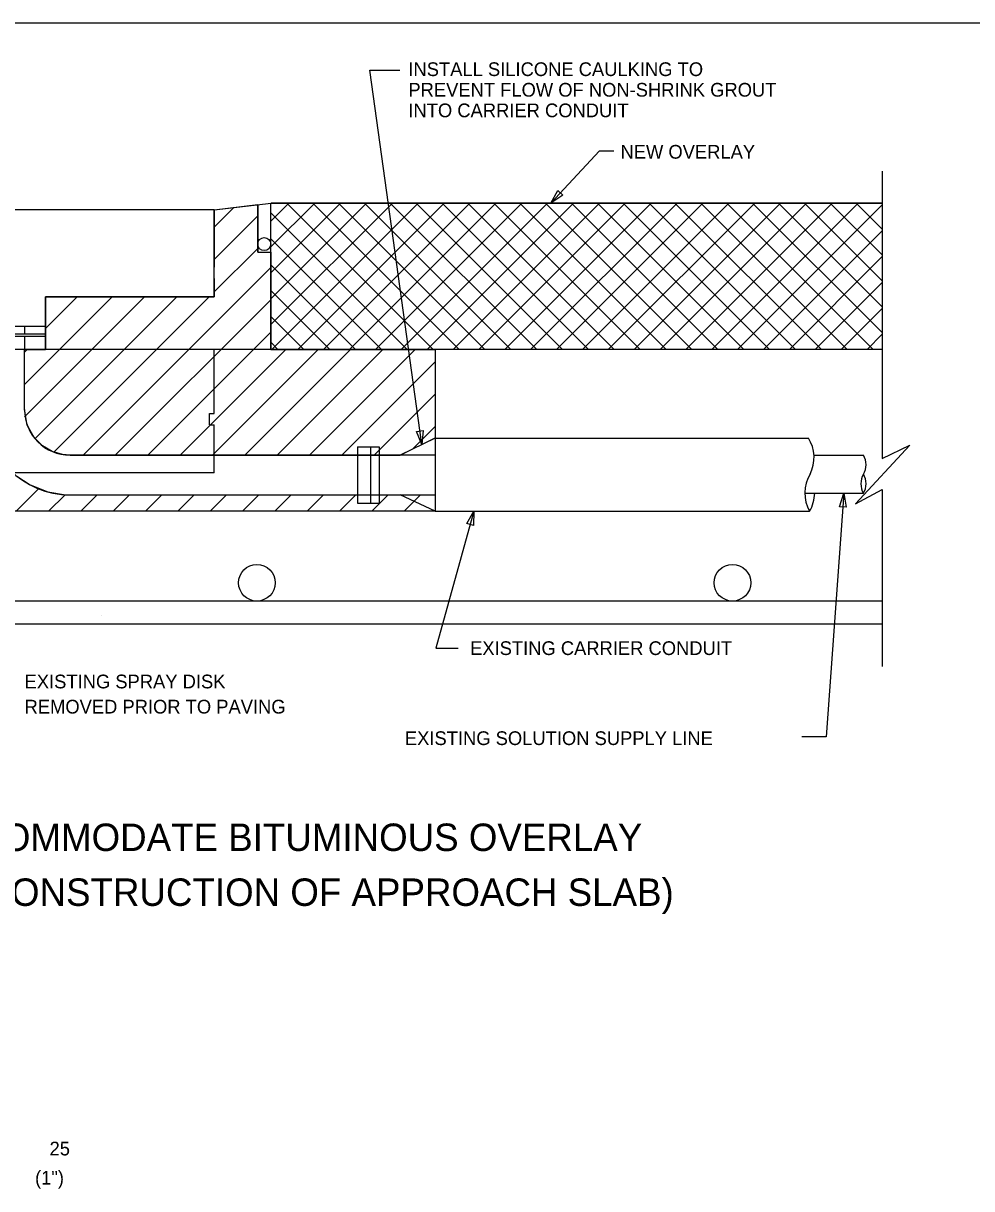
# Model space of a CAD drawing. Extents: x 3239 to 4230, y -4276 to -2494.
# Drawn here: x 3464.4 to 3671.7, y -3952 to -3697.3 of the extents above; entities that cross this region are included whole.
import ezdxf

# ---------------------------------------------------------------- set-up
doc = ezdxf.new("R2010")
doc.units = 0
for name, color, linetype in [('1', 7, 'Continuous'), ('2', 7, 'Continuous'), ('3', 7, 'Continuous')]:
    doc.layers.add(name, color=color, linetype=linetype)

msp = doc.modelspace()

# ---------------------------------------------------------------- linework, layer by layer
at = {"layer": '2'}
for p, q in [((4065.03, -3697.29), (3279.03, -3697.29)), ((3652.12, -3729.58), (3652.12, -3792.42)), ((3506.07, -3738.07), (3518.57, -3736.57)), ((3515.6, -3747.29), (3515.6, -3736.93)), ((3518.47, -3768.57), (3518.47, -3736.57)), ((3518.47, -3740.52), (3522.41, -3736.57)), ((3518.47, -3746.17), (3528.07, -3736.57)), ((3518.47, -3751.83), (3533.73, -3736.57)), ((3518.47, -3757.49), (3539.38, -3736.57)), ((3518.47, -3763.14), (3545.04, -3736.57)), ((3652.12, -3736.57), (3518.57, -3736.57)), ((3518.7, -3768.57), (3550.7, -3736.57)), ((3521.96, -3736.57), (3553.96, -3768.57)), ((3524.35, -3768.57), (3556.35, -3736.57)), ((3527.62, -3736.57), (3559.62, -3768.57)), ((3530.01, -3768.57), (3562.01, -3736.57)), ((3533.28, -3736.57), (3565.28, -3768.57)), ((3535.67, -3768.57), (3567.67, -3736.57)), ((3538.93, -3736.57), (3570.93, -3768.57)), ((3541.33, -3768.57), (3573.33, -3736.57)), ((3544.59, -3736.57), (3576.59, -3768.57)), ((3546.98, -3768.57), (3578.98, -3736.57)), ((3550.25, -3736.57), (3582.25, -3768.57)), ((3552.64, -3768.57), (3584.64, -3736.57)), ((3555.9, -3736.57), (3587.9, -3768.57)), ((3558.3, -3768.57), (3590.3, -3736.57)), ((3561.56, -3736.57), (3593.56, -3768.57)), ((3563.95, -3768.57), (3595.95, -3736.57)), ((3567.22, -3736.57), (3599.22, -3768.57)), ((3569.61, -3768.57), (3601.61, -3736.57)), ((3572.88, -3736.57), (3604.88, -3768.57)), ((3575.27, -3768.57), (3607.27, -3736.57)), ((3578.53, -3736.57), (3610.53, -3768.57)), ((3580.92, -3768.57), (3612.92, -3736.57)), ((3584.19, -3736.57), (3616.19, -3768.57)), ((3586.58, -3768.57), (3618.58, -3736.57)), ((3589.85, -3736.57), (3621.85, -3768.57)), ((3592.24, -3768.57), (3624.24, -3736.57)), ((3595.5, -3736.57), (3627.5, -3768.57)), ((3597.89, -3768.57), (3629.89, -3736.57)), ((3601.16, -3736.57), (3633.16, -3768.57)), ((3603.55, -3768.57), (3635.55, -3736.57)), ((3606.82, -3736.57), (3638.82, -3768.57)), ((3609.21, -3768.57), (3641.21, -3736.57)), ((3612.47, -3736.57), (3644.47, -3768.57)), ((3614.86, -3768.57), (3646.86, -3736.57)), ((3618.13, -3736.57), (3650.13, -3768.57)), ((3620.52, -3768.57), (3652.12, -3736.98)), ((3623.79, -3736.57), (3652.12, -3764.9)), ((3629.44, -3736.57), (3652.12, -3759.24)), ((3635.1, -3736.57), (3652.12, -3753.59)), ((3640.76, -3736.57), (3652.12, -3747.93)), ((3646.41, -3736.57), (3652.12, -3742.27)), ((3652.07, -3736.57), (3652.12, -3736.62)), ((3506.07, -3738.07), (3378.57, -3738.07)), ((3506.07, -3741.87), (3510.38, -3737.56)), ((3506.07, -3757.07), (3506.07, -3738.07)), ((3506.07, -3738.07), (3506.07, -3750.57)), ((3506.07, -3748.92), (3515.6, -3739.38)), ((3518.47, -3738.74), (3548.31, -3768.57)), ((3518.47, -3744.39), (3542.65, -3768.57)), ((3626.18, -3768.57), (3652.12, -3742.64)), ((3506.07, -3756.01), (3515.6, -3746.48)), ((3515.6, -3747.29), (3518.47, -3747.29)), ((3631.84, -3768.57), (3652.12, -3748.29)), ((3500.56, -3768.57), (3518.47, -3750.66)), ((3518.47, -3750.05), (3536.99, -3768.57)), ((3506.07, -3753.07), (3506.07, -3757.07)), ((3637.49, -3768.57), (3652.12, -3753.95)), ((3464.62, -3783.32), (3490.86, -3757.07)), ((3506.07, -3757.07), (3469.21, -3757.07)), ((3469.21, -3757.07), (3469.21, -3768.57)), ((3469.21, -3763.98), (3476.12, -3757.07)), ((3471.04, -3791.04), (3505.01, -3757.07)), ((3472.27, -3768.57), (3483.77, -3757.07)), ((3486.41, -3768.57), (3497.91, -3757.07)), ((3518.47, -3755.71), (3531.34, -3768.57)), ((3484.48, -3791.7), (3518.47, -3757.71)), ((3518.47, -3758.74), (3518.47, -3768.57)), ((3643.15, -3768.57), (3652.12, -3759.61)), ((3518.47, -3761.36), (3525.68, -3768.57)), ((3469.21, -3763.57), (3415.47, -3763.57)), ((3468.97, -3763.57), (3415.47, -3763.57)), ((3451.73, -3765.2), (3469.21, -3765.2)), ((3464.62, -3763.57), (3464.62, -3765.2)), ((3469.21, -3762.95), (3469.21, -3765.2)), ((3514.7, -3768.57), (3518.47, -3764.8)), ((3451.73, -3765.7), (3469.21, -3765.7)), ((3464.62, -3765.7), (3464.62, -3768.57)), ((3469.21, -3765.7), (3469.21, -3768.57)), ((3518.47, -3767.02), (3520.02, -3768.57)), ((3648.81, -3768.57), (3652.12, -3765.26)), ((3518.47, -3768.57), (3447.87, -3768.57)), ((3464.62, -3781.7), (3464.62, -3768.57)), ((3464.62, -3776.22), (3472.27, -3768.57)), ((3464.62, -3769.17), (3465.22, -3768.57)), ((3466.94, -3788.05), (3486.41, -3768.57)), ((3477.43, -3791.7), (3500.56, -3768.57)), ((3491.57, -3791.7), (3514.7, -3768.57)), ((3498.62, -3791.7), (3521.75, -3768.57)), ((3505.71, -3791.7), (3528.84, -3768.57)), ((3506.07, -3782.57), (3506.07, -3768.57)), ((3512.76, -3791.7), (3535.89, -3768.57)), ((3652.12, -3768.57), (3518.57, -3768.57)), ((3519.85, -3791.7), (3542.98, -3768.57)), ((3526.9, -3791.7), (3550.03, -3768.57)), ((3554.39, -3768.57), (3554.37, -3803.92)), ((3534, -3791.7), (3554.38, -3771.31)), ((3541.05, -3791.7), (3554.38, -3778.37)), ((3505.07, -3782.57), (3506.07, -3782.57)), ((3505.07, -3785.07), (3505.07, -3782.57)), ((3505.07, -3785.07), (3506.07, -3785.07)), ((3506.07, -3795.57), (3506.07, -3785.07)), ((3549.47, -3790.37), (3554.38, -3785.46)), ((3554.38, -3787.94), (3635.98, -3787.94)), ((3537.39, -3789.87), (3537.39, -3802.21)), ((3537.39, -3789.87), (3542.15, -3789.87)), ((3540.23, -3789.87), (3540.23, -3802.21)), ((3542.15, -3789.87), (3542.15, -3802.21)), ((3658.15, -3789.51), (3646.25, -3802.3)), ((3652.12, -3792.42), (3658.15, -3789.51)), ((3474.62, -3791.7), (3546.77, -3791.7)), ((3637.22, -3791.71), (3648.02, -3791.71)), ((3506.07, -3795.57), (3378.57, -3795.57)), ((3462.82, -3803.94), (3467.71, -3799.05)), ((3469.87, -3803.94), (3473.48, -3800.33)), ((3474.62, -3800.38), (3546.77, -3800.38)), ((3476.96, -3803.94), (3480.53, -3800.38)), ((3484.01, -3803.94), (3487.58, -3800.38)), ((3491.1, -3803.94), (3494.67, -3800.38)), ((3498.15, -3803.94), (3501.72, -3800.38)), ((3505.2, -3803.94), (3508.77, -3800.38)), ((3512.3, -3803.94), (3515.86, -3800.38)), ((3519.35, -3803.94), (3522.91, -3800.38)), ((3526.44, -3803.94), (3530, -3800.38)), ((3533.49, -3803.94), (3537.05, -3800.38)), ((3540.58, -3803.94), (3544.15, -3800.38)), ((3547.63, -3803.94), (3551.2, -3800.38)), ((3635.21, -3800.02), (3648.02, -3800.02)), ((3646.25, -3802.3), (3652.12, -3799.17)), ((3652.12, -3799.17), (3652.12, -3837.88)), ((3537.39, -3802.21), (3542.15, -3802.21)), ((3554.37, -3803.94), (3636.23, -3803.94)), ((3652.12, -3823.61), (3314.21, -3823.61)), ((3652.12, -3828.61), (3314.21, -3828.61))]:
    msp.add_line(p, q, dxfattribs=at)
for points in [[(3551.45, -3789.37), (3540.11, -3707.55), (3546.67, -3707.55)], [(3579.68, -3736.57), (3590.32, -3725.13), (3593.42, -3725.13)], [(3462.98, -3796.31), (3465.89, -3798.21), (3469.73, -3799.73), (3473.57, -3800.35), (3474.62, -3800.38), (3554.37, -3800.38), (3554.37, -3803.94), (3366.07, -3803.94)], [(3643.74, -3800.02), (3639.87, -3853.29), (3634.56, -3853.27)], [(3562.87, -3803.94), (3554.52, -3833.91), (3559.45, -3833.91)]]:
    msp.add_lwpolyline(points, dxfattribs=at)
for points in [[(3582.27, -3734.89), (3579.68, -3736.57), (3581.18, -3733.86)], [(3506.07, -3738.07), (3515.6, -3736.93), (3515.6, -3747.29), (3518.47, -3747.29), (3518.47, -3768.57), (3554.39, -3768.57), (3554.38, -3787.94), (3546.77, -3791.7), (3474.62, -3791.7), (3472.95, -3791.56), (3470.67, -3790.89), (3468.59, -3789.68), (3466.74, -3787.85), (3465.23, -3785.15), (3464.62, -3781.7), (3464.62, -3768.57), (3469.21, -3768.57), (3469.21, -3768.57), (3469.21, -3757.07), (3506.07, -3757.07)], [(3518.47, -3736.57), (3652.12, -3736.57), (3652.12, -3768.57), (3518.47, -3768.57), (3518.47, -3747.29)], [(3554.38, -3787.92), (3554.37, -3791.7), (3546.77, -3791.7)], [(3551.78, -3786.3), (3551.45, -3789.37), (3550.29, -3786.5)], [(3546.74, -3800.38), (3554.37, -3800.38), (3554.37, -3803.92)], [(3642.78, -3802.96), (3643.74, -3800.02), (3644.27, -3803.07)], [(3561.35, -3806.63), (3562.87, -3803.94), (3562.79, -3807.04)]]:
    msp.add_lwpolyline(points, close=True, dxfattribs=at)
for centre, radius in [((3517.04, -3745.55), 1.43), ((3515.42, -3819.59), 4), ((3619.39, -3819.59), 4)]:
    msp.add_circle(centre, radius, dxfattribs=at)
for centre, radius, start, end in [((3474.62, -3781.7), 18.68, 180, 270), ((3474.62, -3781.7), 10, 180, 270), ((3629.3, -3792.23), 7.93, 332.7154, 32.7154), ((3644.42, -3793.79), 4.16, 330, 30), ((3643.29, -3800.01), 8.08, 149.1201, 209.1201), ((3651.62, -3797.95), 4.16, 150, 210), ((3644.42, -3797.95), 4.16, 330, 30), ((3629.3, -3799.8), 8.08, 329.1201, 358.4019), ((3461.52, -3826.85), 20, 0, 2.777777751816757e-06)]:
    msp.add_arc(centre, radius, start, end, dxfattribs=at)

# ---------------------------------------------------------------- texts
at = {"layer": '1'}
msp.add_text('(1")', height=3, dxfattribs=at).set_placement((3466.93, -3951.14))
at = {"layer": '2'}
for s, height, p in [('INSTALL SILICONE CAULKING TO ', 3, (3548.54, -3708.82)), ('PREVENT FLOW OF NON-SHRINK GROUT', 3, (3548.54, -3713.32)), ('INTO CARRIER CONDUIT', 3, (3548.54, -3717.82)), ('NEW OVERLAY ', 3, (3594.91, -3726.88)), ('EXISTING CARRIER CONDUIT', 3, (3562.03, -3835.38)), ('EXISTING SPRAY DISK', 3, (3464.64, -3842.67)), ('REMOVED PRIOR TO PAVING', 3, (3464.64, -3848.17)), ('EXISTING SOLUTION SUPPLY LINE', 3, (3547.78, -3855.06)), ('SPRAY DISC ADJUSTMENT TO ACCOMMODATE BITUMINOUS OVERLAY', 6, (3322.38, -3878.22)), ('(ORIGINAL SPRAY DISK INSTALLED AFTER CONSTRUCTION OF APPROACH SLAB)', 6, (3287.79, -3890.22))]:
    msp.add_text(s, height=height, dxfattribs=at).set_placement(p)
at = {"layer": '3'}
msp.add_text('25', height=3, dxfattribs=at).set_placement((3470.1, -3944.77))

doc.saveas('drawing.dxf')
